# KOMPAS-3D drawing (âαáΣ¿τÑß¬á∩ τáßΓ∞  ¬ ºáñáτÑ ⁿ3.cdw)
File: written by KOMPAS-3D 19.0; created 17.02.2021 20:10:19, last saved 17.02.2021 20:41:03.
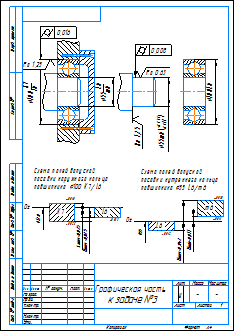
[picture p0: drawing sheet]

Sheet 1: A4, portrait

Document properties: Автор: Юрий; Полное имя файла: C:\Users\Юрий\Desktop\метрология сироп\Графическая часть  к задаче №3.cdw

Title block, sheet 1: Наименование: Графическая часть / к задаче №3; Количество листов документа: 1; Форматы листов документа: A4; Литера: у

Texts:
  Схема полей допусков
  посадки наружного кольца
  подшипника  100 К7/l6
  посадки нутреннего кольца
  подшипника  55 L6/m6
  Ra 1,25
  Ra 0.63
Dimensions and other numbers on the sheet: +0,010; -0,025; -0,013; 120; 55; -0,012; +0,011; +0,030; 100; 0,016; 0,008; 1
